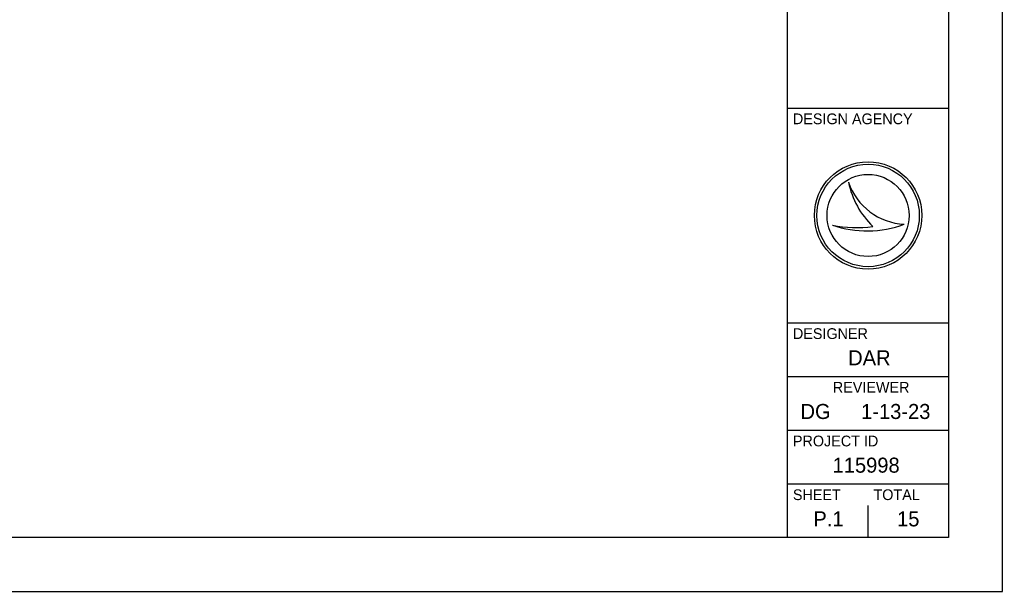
# Model space of a CAD drawing. Extents: x -5.6 to 34, y 0 to 22.
# Drawn here: x 24.85 to 34, y 0 to 5.32 of the extents above; entities that cross this region are included whole.
import ezdxf

# ---------------------------------------------------------------- set-up
doc = ezdxf.new("R2010")
doc.units = 0
for name, color, linetype in [('SH_Border', 7, 'Continuous'), ('SH_Cut_Line', 7, 'Continuous'), ('SH_Data', 7, 'Continuous')]:
    doc.layers.add(name, color=color, linetype=linetype)

msp = doc.modelspace()

# ---------------------------------------------------------------- linework, layer by layer
at = {"layer": 'SH_Border'}
for p, q in [((32, 0.5), (32, 21.5)), ((32, 4.5), (33.5, 4.5)), ((32, 2.5), (33.5, 2.5)), ((32, 2), (33.5, 2)), ((32, 1.5), (33.5, 1.5)), ((32, 1), (33.5, 1))]:
    msp.add_line(p, q, dxfattribs=at)
msp.add_lwpolyline([(1.5, 21.5), (33.5, 21.5), (33.5, 0.5), (1.5, 0.5)], close=True, dxfattribs=at)
at = {"layer": 'SH_Cut_Line'}
msp.add_lwpolyline([(0, 0), (34, 0), (34, 22), (0, 22)], close=True, dxfattribs=at)
at = {"layer": 'SH_Data'}
for p, q in [((32.5674, 3.8096), (32.5675, 3.8096)), ((32.5674, 3.8096), (32.5675, 3.8096)), ((32.75, 3.5), (32.75, 3.5)), ((32.4172, 3.4095), (32.4172, 3.4095)), ((32.4172, 3.4095), (32.4172, 3.4095)), ((33.0873, 3.4185), (33.0873, 3.4185)), ((33.0873, 3.4185), (33.0873, 3.4185)), ((32.75, 0.5), (32.75, 0.8)), ((32.375, 0.675), (32.375, 0.675))]:
    msp.add_line(p, q, dxfattribs=at)
for radius in [0.5, 0.5, 0.4768, 0.4768, 0.4768, 0.4768, 0.3822, 0.3822]:
    msp.add_circle((32.75, 3.5), radius, dxfattribs=at)
for centre, radius, start, end in [((33.1159, 3.9976), 0.5798, 198.92567, 198.93195), ((33.1159, 3.9976), 0.5798, 198.92567, 198.93195), ((33.3467, 3.9701), 0.7956, 191.63793, 191.64215), ((33.3467, 3.9701), 0.7956, 191.63793, 191.64215), ((33.1159, 3.9976), 0.5798, 198.93195, 267.16574), ((33.3467, 3.9701), 0.7956, 191.64215, 226.09467), ((33.1159, 3.9976), 0.5798, 198.93195, 267.16574), ((33.3467, 3.9701), 0.7956, 191.64215, 226.09467), ((32.7394, 4.37), 1.0131, 251.45764, 290.08324), ((32.7394, 4.37), 1.0131, 251.45764, 290.08324), ((32.648, 4.6543), 1.2661, 259.49639, 259.49952), ((32.7394, 4.37), 1.0131, 251.45274, 251.45764), ((32.648, 4.6543), 1.2661, 259.49952, 276.66723), ((32.648, 4.6543), 1.2661, 259.49639, 259.49952), ((32.7394, 4.37), 1.0131, 251.45274, 251.45764), ((32.648, 4.6543), 1.2661, 259.49952, 276.66723)]:
    msp.add_arc(centre, radius, start, end, dxfattribs=at)

# ---------------------------------------------------------------- texts
for s, height, p in [('DESIGN AGENCY', 0.1, (32.05, 4.35)), ('DESIGNER', 0.1, (32.05, 2.35)), ('DAR', 0.14, (32.5643, 2.105)), ('REVIEWER', 0.1, (32.4218, 1.85)), ('DG', 0.14, (32.1206, 1.605)), ('1-13-23', 0.14, (32.6848, 1.605)), ('PROJECT ID', 0.1, (32.05, 1.35)), ('115998', 0.14, (32.4193, 1.105)), ('SHEET', 0.1, (32.05, 0.85)), ('TOTAL', 0.1, (32.8, 0.85)), ('P.1', 0.14, (32.2403, 0.605)), ('15', 0.14, (33.0197, 0.605))]:
    msp.add_text(s, height=height, dxfattribs=at).set_placement(p)

doc.saveas('drawing.dxf')
